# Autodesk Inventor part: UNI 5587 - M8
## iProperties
Library Location: C:\Programmi\Autodesk\Inventor 6\content
Library: local
SubLibrary: UNI
Family: 52
Member: 6
Member Major Revision: 1
Member Minor Revision: 1
Comments: To add or edit properties for Autodesk Inventor files, use iProperties.
Created: 2004-01
Part Number: UNI 5587 - M8
Vendor: Autodesk Inc.
Document SubType Name: Modeling
Designer: Lollo
Description: Dado esagonale
Standard: UNI 5587 M8
Alert: To add or edit properties for Autodesk Inventor files, use iProperties.
Control State: 0
Master: False
Checked Out: False
Shininess: 64.0
Length Units: 11269
Angle Units: 11279
Time Units: 11290
Mass Units: 11283
Length Display Precision: 3
Angle Display Precision: 2
Compacted: True
EGR: 1
Density: 0.0
Volumn: 0.0
Area: 0.0
PropertySet Name: Model Information
Author: Lollo
Revision Number: 1
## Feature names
1. Corpo [Extrusion]
2. Smusso1 [Revolution]
3. Filettatura [Hole]
4. Smusso2 [Chamfer]
5. Smusso3 [Chamfer]
